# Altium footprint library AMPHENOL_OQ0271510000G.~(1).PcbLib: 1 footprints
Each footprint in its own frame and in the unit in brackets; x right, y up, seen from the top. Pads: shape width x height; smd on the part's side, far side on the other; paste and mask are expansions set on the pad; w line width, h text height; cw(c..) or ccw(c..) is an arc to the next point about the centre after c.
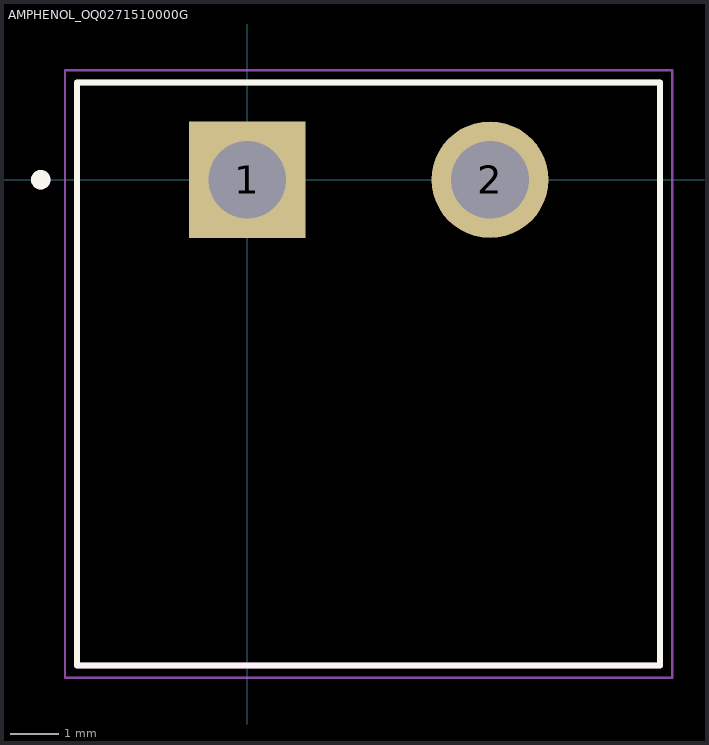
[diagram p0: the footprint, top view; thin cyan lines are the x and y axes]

## AMPHENOL_OQ0271510000G [mm]
height 8.5
pads (2):
  rect 2.4x2.4 / inner round 2.4 / far side rect 2.4x2.4 hole 1.6: 1(0,0)
  round 2.4 hole 1.6: 2(5,0)
Top Overlay:
  circle w0.2: c-4.25,0 r0.1
  lines w0.127: -3.5,-10 8.5,-10 8.5,2 -3.5,2 -3.5,-10
Assembly Top:
  circle w0.2: c-4.25,0 r0.1
  lines w0.127: -3.5,-10 8.5,-10 8.5,2 -3.5,2 -3.5,-10
Courtyard Top:
  lines w0.05: -3.75,-10.25 8.75,-10.25 8.75,2.25 -3.75,2.25 -3.75,-10.25
3D body "step_temp.STEP": height 8.5, standoff -3.5, extent -3.5,-10 8.5,2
